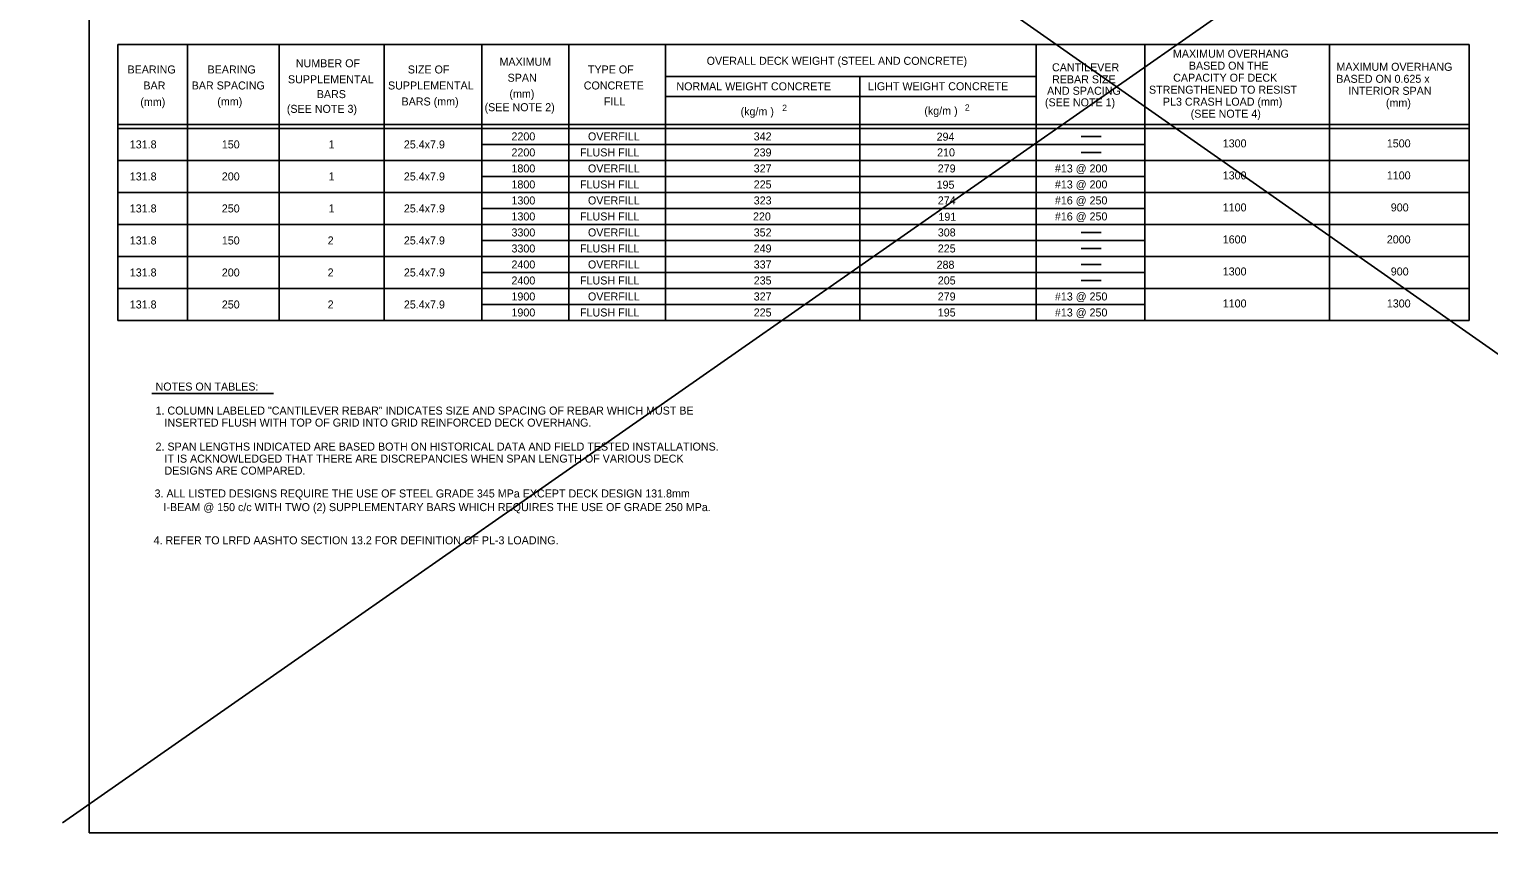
# Model space of a CAD drawing. Extents: x -24512 to -22484, y 4569 to 6351.
# Drawn here: x -23319 to -22772, y 5769 to 6073 of the extents above; entities that cross this region are included whole.
import ezdxf

# ---------------------------------------------------------------- set-up
doc = ezdxf.new("R2010")
doc.units = 0
for name, color, linetype in [('10', 7, 'Continuous'), ('2', 7, 'Continuous'), ('3', 7, 'Continuous'), ('6', 7, 'Continuous')]:
    doc.layers.add(name, color=color, linetype=linetype)

msp = doc.modelspace()

# ---------------------------------------------------------------- linework, layer by layer
at = {"layer": '10'}
for p, q in [((-23319.32, 6337.49), (-22508.07, 5768.63)), ((-22515.22, 6328.54), (-23306.81, 5775.78)), ((-22925, 6033.04), (-22917.5, 6033.04)), ((-22925, 6027.04), (-22917.5, 6027.04)), ((-22925, 5997.04), (-22917.5, 5997.04)), ((-22925, 5991.04), (-22917.5, 5991.04)), ((-22925, 5985.04), (-22917.5, 5985.04)), ((-22925, 5979.04), (-22917.5, 5979.04))]:
    msp.add_line(p, q, dxfattribs=at)
at = {"layer": '2'}
for p, q in [((-23296.79, 5772.04), (-23296.79, 6334.63)), ((-22512.75, 5772.04), (-23296.79, 5772.04))]:
    msp.add_line(p, q, dxfattribs=at)
at = {"layer": '3'}
for p, q in [((-23286.11, 5964.04), (-23286.11, 6067.54)), ((-23286.11, 6067.54), (-22779.5, 6067.54)), ((-23259.99, 5964.04), (-23259.99, 6067.54)), ((-23225.67, 5964.04), (-23225.67, 6067.54)), ((-23186.24, 5964.04), (-23186.24, 6067.54)), ((-23149.67, 5964.04), (-23149.67, 6067.54)), ((-23117.09, 5964.04), (-23117.09, 6067.54)), ((-23080.77, 5964.04), (-23080.77, 6067.54)), ((-22941.84, 5964.04), (-22941.84, 6067.54)), ((-22901.17, 5964.04), (-22901.17, 6067.54)), ((-22831.95, 5964.04), (-22831.95, 6067.54)), ((-22779.5, 5964.04), (-22779.5, 6067.54)), ((-22941.84, 6055.5), (-23080.77, 6055.5)), ((-23008.01, 5964.04), (-23008.01, 6055.5)), ((-22941.84, 6047.97), (-23080.77, 6047.97)), ((-23286.11, 6037.54), (-22779.5, 6037.54)), ((-23286.11, 6036.04), (-22779.5, 6036.04)), ((-23149.67, 6030.04), (-22901.17, 6030.04)), ((-23286.11, 6024.04), (-23149.67, 6024.04)), ((-23149.61, 6024.04), (-22779.5, 6024.04)), ((-23149.67, 6018.04), (-22901.17, 6018.04)), ((-23286.11, 6012.04), (-23149.67, 6012.04)), ((-23149.61, 6012.04), (-22779.5, 6012.04)), ((-23149.67, 6006.04), (-22901.17, 6006.04)), ((-23286.11, 6000.04), (-23149.67, 6000.04)), ((-23149.61, 6000.04), (-22779.5, 6000.04)), ((-23149.67, 5994.04), (-22901.17, 5994.04)), ((-23286.11, 5988.04), (-23149.67, 5988.04)), ((-23149.61, 5988.04), (-22779.5, 5988.04)), ((-23149.67, 5982.04), (-22901.17, 5982.04)), ((-23286.11, 5976.04), (-23149.67, 5976.04)), ((-23149.61, 5976.04), (-22779.5, 5976.04)), ((-23149.67, 5970.04), (-22901.17, 5970.04)), ((-23286.11, 5964.04), (-22779.5, 5964.04))]:
    msp.add_line(p, q, dxfattribs=at)
at = {"layer": '6'}
msp.add_line((-23273.4, 5936.61), (-23227.74, 5936.61), dxfattribs=at)

# ---------------------------------------------------------------- texts
at = {"layer": '10'}
for s, p in [('1300', (-22871.93, 6028.92)), ('1500', (-22810.43, 6028.92)), ('#13 @ 200', (-22934.85, 6019.54)), ('1300', (-22871.93, 6016.92)), ('1100', (-22810.43, 6016.92)), ('#13 @ 200', (-22934.85, 6013.54)), ('#16 @ 250', (-22934.85, 6007.54)), ('1100', (-22871.93, 6004.92)), ('900', (-22808.94, 6004.92)), ('#16 @ 250', (-22934.85, 6001.54)), ('1600', (-22871.93, 5992.92)), ('2000', (-22810.43, 5992.92)), ('1300', (-22871.93, 5980.92)), ('900', (-22808.94, 5980.92)), ('#13 @ 250', (-22934.85, 5971.54)), ('1100', (-22871.93, 5968.92)), ('1300', (-22810.43, 5968.92)), ('#13 @ 250', (-22934.85, 5965.54))]:
    msp.add_text(s, height=3, dxfattribs=at).set_placement(p)
at = {"layer": '6'}
for s, height, p in [('MAXIMUM', 3, (-23143.03, 6059.53)), ('OVERALL DECK WEIGHT (STEEL AND CONCRETE)', 2.9999, (-23065.37, 6059.87)), ('MAXIMUM OVERHANG', 2.9999, (-22890.6, 6062.55)), ('BEARING', 3, (-23282.46, 6056.63)), ('BEARING', 3, (-23252.46, 6056.63)), ('NUMBER OF', 3, (-23219.37, 6058.95)), ('SIZE OF', 3, (-23177.39, 6056.63)), ('TYPE OF', 3, (-23109.89, 6056.63)), ('CANTILEVER', 3, (-22935.93, 6057.44)), ('CAPACITY OF DECK', 2.9999, (-22890.51, 6053.55)), ('BASED ON THE', 2.9999, (-22884.63, 6058.05)), ('MAXIMUM OVERHANG', 2.9999, (-22829.32, 6057.63)), ('BAR', 3, (-23276.51, 6050.63)), ('BAR SPACING', 2.9999, (-23258.41, 6050.63)), ('SUPPLEMENTAL', 2.9999, (-23222.32, 6052.95)), ('SUPPLEMENTAL', 2.9999, (-23184.82, 6050.63)), ('SPAN', 3, (-23140, 6053.53)), ('CONCRETE', 3, (-23111.44, 6050.63)), ('NORMAL WEIGHT CONCRETE', 2.9999, (-23076.72, 6050.31)), ('LIGHT WEIGHT CONCRETE', 2.9999, (-23004.92, 6050.34)), ('AND SPACING', 2.9999, (-22937.78, 6048.65)), ('REBAR SIZE', 3, (-22935.91, 6052.94)), ('STRENGTHENED TO RESIST', 2.9999, (-22899.58, 6049.05)), ('BASED ON 0.625 x', 2.9999, (-22829.38, 6053.13)), ('INTERIOR SPAN', 2.9999, (-22824.85, 6048.63)), ('(mm)', 3, (-23277.65, 6044.49)), ('(mm)', 3, (-23248.8, 6044.63)), ('BARS', 3, (-23211.52, 6047.39)), ('BARS (mm)', 3, (-23179.74, 6044.63)), ('(SEE NOTE 2)', 2.9999, (-23148.62, 6042.49)), ('(mm)', 3, (-23139.3, 6047.53)), ('FILL', 3, (-23103.91, 6044.63)), ('(SEE NOTE 1)', 2.9999, (-22938.57, 6044.31)), ('PL3 CRASH LOAD (mm)', 2.9999, (-22894.36, 6044.55)), ('(mm)', 3, (-22810.76, 6044.13)), ('(SEE NOTE 3)', 2.9999, (-23222.74, 6041.87)), ('(kg/m )', 3, (-23052.65, 6040.91)), ('2', 2.39, (-23037.06, 6042.53)), ('(kg/m )', 3, (-22983.78, 6041.17)), ('2', 2.39, (-22968.59, 6042.66)), ('(SEE NOTE 4)', 2.9999, (-22883.95, 6040.05)), ('131.8', 3, (-23281.61, 6028.54)), ('150', 3, (-23247.11, 6028.54)), ('1', 3, (-23207.11, 6028.54)), ('25.4x7.9', 3, (-23178.88, 6028.54)), ('2200', 3, (-23138.54, 6031.54)), ('OVERFILL', 3, (-23109.87, 6031.54)), ('342', 3, (-23047.74, 6031.54)), ('294', 3, (-22979.19, 6031.44)), ('2200', 3, (-23138.54, 6025.54)), ('FLUSH FILL', 3, (-23112.84, 6025.54)), ('239', 3, (-23047.76, 6025.54)), ('210', 3, (-22979, 6025.54)), ('131.8', 3, (-23281.61, 6016.54)), ('200', 3, (-23247.11, 6016.54)), ('1', 3, (-23207.11, 6016.54)), ('25.4x7.9', 3, (-23178.88, 6016.54)), ('1800', 3, (-23138.54, 6019.54)), ('OVERFILL', 3, (-23109.87, 6019.54)), ('327', 3, (-23047.74, 6019.54)), ('279', 3, (-22978.76, 6019.54)), ('1800', 3, (-23138.54, 6013.54)), ('FLUSH FILL', 3, (-23112.84, 6013.54)), ('225', 3, (-23047.74, 6013.54)), ('195', 3, (-22979.19, 6013.44)), ('131.8', 3, (-23281.61, 6004.54)), ('250', 3, (-23247.11, 6004.54)), ('1', 3, (-23207.11, 6004.54)), ('25.4x7.9', 3, (-23178.88, 6004.54)), ('1300', 3, (-23138.54, 6007.54)), ('OVERFILL', 3, (-23109.87, 6007.54)), ('323', 3, (-23047.74, 6007.54)), ('274', 3, (-22978.74, 6007.54)), ('1300', 3, (-23138.54, 6001.54)), ('FLUSH FILL', 3, (-23112.84, 6001.54)), ('220', 3, (-23048, 6001.54)), ('191', 3, (-22978.51, 6001.44)), ('3300', 3, (-23138.54, 5995.54)), ('OVERFILL', 3, (-23109.87, 5995.54)), ('352', 3, (-23047.74, 5995.54)), ('308', 3, (-22978.74, 5995.54)), ('131.8', 3, (-23281.61, 5992.54)), ('150', 3, (-23247.11, 5992.54)), ('2', 3, (-23207.45, 5992.54)), ('25.4x7.9', 3, (-23178.88, 5992.54)), ('3300', 3, (-23138.54, 5989.54)), ('FLUSH FILL', 3, (-23112.84, 5989.54)), ('249', 3, (-23047.76, 5989.54)), ('225', 3, (-22978.74, 5989.54)), ('2400', 3, (-23138.54, 5983.54)), ('OVERFILL', 3, (-23109.87, 5983.54)), ('337', 3, (-23047.74, 5983.54)), ('288', 3, (-22979.19, 5983.44)), ('131.8', 3, (-23281.61, 5980.54)), ('200', 3, (-23247.11, 5980.54)), ('2', 3, (-23207.45, 5980.54)), ('25.4x7.9', 3, (-23178.88, 5980.54)), ('2400', 3, (-23138.54, 5977.54)), ('FLUSH FILL', 3, (-23112.84, 5977.54)), ('235', 3, (-23047.74, 5977.54)), ('205', 3, (-22978.74, 5977.54)), ('1900', 3, (-23138.54, 5971.54)), ('OVERFILL', 3, (-23109.87, 5971.54)), ('327', 3, (-23047.74, 5971.54)), ('279', 3, (-22978.76, 5971.54)), ('131.8', 3, (-23281.61, 5968.54)), ('250', 3, (-23247.11, 5968.54)), ('2', 3, (-23207.45, 5968.54)), ('25.4x7.9', 3, (-23178.88, 5968.54)), ('1900', 3, (-23138.54, 5965.54)), ('FLUSH FILL', 3, (-23112.84, 5965.54)), ('225', 3, (-23047.74, 5965.54)), ('195', 3, (-22978.74, 5965.54)), ('NOTES ON TABLES:', 2.9999, (-23271.95, 5937.77)), ('1. COLUMN LABELED "CANTILEVER REBAR" INDICATES SIZE AND SPACING OF REBAR WHICH MUST BE', 2.9999, (-23271.95, 5928.77)), ('   INSERTED FLUSH WITH TOP OF GRID INTO GRID REINFORCED DECK OVERHANG.', 2.9999, (-23271.95, 5924.27)), ('2. SPAN LENGTHS INDICATED ARE BASED BOTH ON HISTORICAL DATA AND FIELD TESTED INSTALLATIONS.', 2.9999, (-23271.95, 5915.27)), ('   DESIGNS ARE COMPARED.', 2.9999, (-23271.95, 5906.27)), ('   IT IS ACKNOWLEDGED THAT THERE ARE DISCREPANCIES WHEN SPAN LENGTH OF VARIOUS DECK', 2.9999, (-23271.95, 5910.77)), ('3. ALL LISTED DESIGNS REQUIRE THE USE OF STEEL GRADE 345 MPa EXCEPT DECK DESIGN 131.8mm', 2.9999, (-23272.32, 5897.7)), ('   I-BEAM @ 150 c/c WITH TWO (2) SUPPLEMENTARY BARS WHICH REQUIRES THE USE OF GRADE 250 MPa.', 2.9999, (-23272.32, 5892.58)), ('4. REFER TO LRFD AASHTO SECTION 13.2 FOR DEFINITION OF PL-3 LOADING.', 2.9999, (-23272.69, 5880.14))]:
    msp.add_text(s, height=height, dxfattribs=at).set_placement(p)

doc.saveas('drawing.dxf')
